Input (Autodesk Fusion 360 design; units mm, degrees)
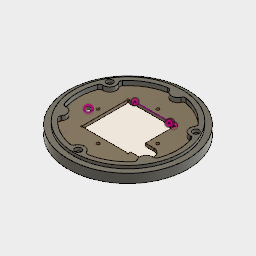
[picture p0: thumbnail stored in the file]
parameter "height" = 12 comment "height of the component"
parameter "rail_height" = 3
parameter "exrtusion_delta_for_magnets" = 0.8
parameter "diameter" = 120
parameter "inner_diameter" = 100
parameter "diameter_offet" = 10
parameter "pressfit_offset" = 1
parameter "magnet_diameter" = 6.4
parameter "magnet_height" = 3.2
parameter "holes_position_from_diameter" = 20
parameter "plateform_height" = 3 (= "height / 4")
parameter "plateform_inner_diameter" = 0
sketch "base" plane through (0, 0, 0) normal (0, 1, 0) x axis (1, 0, 0)
  circle C1 centre (0, 0) radius 60
  circle C2 centre (0, 0) radius 50
  dimension "d1" diameter C1 = 120 (= "diameter")
  dimension "d63" diameter C2 = 100 (= "inner_diameter")
sketch "arround magnets" plane through (0, 0, 0) normal (0, 1, 0) x axis (1, 0, 0)
  circle C1 centre (0, 50) radius 6.4
  point P1 (0, 0)
  point P2 (0, 50)
  dimension "d124" diameter C1 = 12.8 (= "magnet_diameter * 2")
  dimension "d130" distance P1 P2 = 50 (= "diameter / 2 - holes_position_from_diameter / 2")
extrude "Extrude18" new body sketch "arround magnets" along normal blind 12 (= "height")
circular_pattern "C-Pattern6" TotalAngle 360
extrude "Extrude17" new body sketch "base" profile of C2 along normal blind 12 (= "height")
extrude "Extrude8" new body sketch "base" along normal blind 12 (= "height")
combine "Combine2"
sketch "top_holes" plane through (0, 12, 0) normal (0, 1, 0) x axis (-1, 0, 0)
  circle C1 centre (0, 50) radius 3.2
  circle C2 centre (-43.3013, -25) radius 3.2
  circle C3 centre (43.3013, -25) radius 3.2
  point P1 (0, 0)
  point P4 (43.3013, -25)
  dimension "d5" diameter C1 = 6.4 (= "magnet_diameter")
  dimension "d94" distance P1 P4 = 50 (= "diameter / 2 - holes_position_from_diameter / 2")
  dimension "d7" C-Pattern1-Angle = 360
extrude "Extrude13" cut sketch "top_holes" no distance stored
sketch "top_rail_out" plane through (0, 12, 0) normal (0, 1, 0) x axis (-1, 0, 0)
  circle C1 centre (0, 0) radius 60
  circle C2 centre (0, 0) radius 54.5
  circle C3 centre (-43.3013, -25) radius 3.2
  circle C4 centre (0, 50) radius 3.2
  circle C5 centre (43.3013, -25) radius 3.2
  arc A1 centre (-43.3013, 25) radius 6.4 clockwise from (-39.7531, 30.3264) to (-46.14, 19.264)
  arc A2 centre (0, 50) radius 6.4 clockwise from (6.3869, 49.5904) to (-6.3869, 49.5904)
  arc A3 centre (43.3013, 25) radius 6.4 clockwise from (46.14, 19.264) to (39.7531, 30.3264)
  arc A4 centre (43.3013, -25) radius 6.4 clockwise from (39.7531, -30.3264) to (46.14, -19.264)
  arc A5 centre (0, -50) radius 6.4 clockwise from (-6.3869, -49.5904) to (6.3869, -49.5904)
  arc A6 centre (-43.3013, -25) radius 6.4 clockwise from (-46.14, -19.264) to (-39.7531, -30.3264)
  arc A7 centre (0, 0) radius 50 clockwise from (-46.14, -19.264) to (-46.14, 19.264)
  arc A8 centre (0, 0) radius 50 clockwise from (-39.7531, 30.3264) to (-6.3869, 49.5904)
  arc A9 centre (0, 0) radius 50 clockwise from (6.3869, 49.5904) to (39.7531, 30.3264)
  arc A10 centre (0, 0) radius 50 clockwise from (46.14, 19.264) to (46.14, -19.264)
  arc A11 centre (0, 0) radius 50 clockwise from (39.7531, -30.3264) to (6.3869, -49.5904)
  arc A12 centre (0, 0) radius 50 clockwise from (-6.3869, -49.5904) to (-39.7531, -30.3264)
  circle C6 centre (0, 0) radius 60
  dimension "d65" diameter C2 = 109 (= "diameter - diameter_offet - pressfit_offset")
  dimension "d96" diameter C1 = 120 (= "diameter")
extrude "Extrude10" cut sketch "top_rail_out" profile of C1 C2 against normal blind 3 (magnitude of "-1 * rail_height")
sketch "bottom_holes" plane through (0, 0, 0) normal (0, -1, 0) x axis (1, 0, 0)
  circle C1 centre (-43.3013, 25) radius 3.2
  point P1 (0, 0)
  point P2 (-43.3013, 25)
  dimension "d57" diameter C1 = 6.4 (= "magnet_diameter")
  dimension "d95" distance P1 P2 = 50 (= "diameter / 2 - holes_position_from_diameter / 2")
extrude "Extrude14" cut sketch "bottom_holes" no distance stored
sketch "top_rail_in" plane through (0, 12, 0) normal (0, 1, 0) x axis (-1, 0, 0)
  circle C1 centre (0, 0) radius 60
  circle C2 centre (0, 0) radius 50
  circle C3 centre (0, 0) radius 60
  arc A1 centre (-43.3013, 25) radius 6.4 clockwise from (-39.7531, 30.3264) to (-46.14, 19.264)
  arc A2 centre (0, 50) radius 6.4 clockwise from (6.3869, 49.5904) to (-6.3869, 49.5904)
  arc A3 centre (43.3013, 25) radius 6.4 clockwise from (46.14, 19.264) to (39.7531, 30.3264)
  arc A4 centre (43.3013, -25) radius 6.4 clockwise from (39.7531, -30.3264) to (46.14, -19.264)
  arc A5 centre (0, -50) radius 6.4 clockwise from (-6.3869, -49.5904) to (6.3869, -49.5904)
  arc A6 centre (-43.3013, -25) radius 6.4 clockwise from (-46.14, -19.264) to (-39.7531, -30.3264)
  circle C4 centre (-43.3013, -25) radius 3.2
  circle C5 centre (0, 50) radius 3.2
  circle C6 centre (43.3013, -25) radius 3.2
  circle C7 centre (0, 0) radius 54.5
  arc A7 centre (0, 0) radius 50 clockwise from (-46.14, -19.264) to (-46.14, 19.264)
  arc A8 centre (0, 0) radius 50 clockwise from (-39.7531, 30.3264) to (-6.3869, 49.5904)
  arc A9 centre (0, 0) radius 50 clockwise from (6.3869, 49.5904) to (39.7531, 30.3264)
  arc A10 centre (0, 0) radius 50 clockwise from (46.14, 19.264) to (46.14, -19.264)
  arc A11 centre (0, 0) radius 50 clockwise from (39.7531, -30.3264) to (6.3869, -49.5904)
  arc A12 centre (0, 0) radius 50 clockwise from (-6.3869, -49.5904) to (-39.7531, -30.3264)
  dimension "d35" diameter C1 = 120 (= "diameter")
  dimension "d64" diameter C2 = 100 (= "inner_diameter")
  dimension "d66" diameter C3 = 120 (= "diameter")
work_plane "WorkPlane1" AlongDistance -6 (= "-1 * height / 2")
work_point "WorkPoint1"
work_axis "WorkAxis1"
circular_pattern "C-Pattern1" TotalAngle 360
sketch "bottom_rail_out" plane through (0, 0, 0) normal (0, -1, 0) x axis (1, 0, 0)
  circle C1 centre (0, 0) radius 55
  circle C2 centre (0, -50) radius 3.2
  circle C3 centre (43.3013, 25) radius 3.2
  circle C4 centre (-43.3013, 25) radius 3.2
  arc A1 centre (0, -50) radius 6.4 clockwise from (-6.3869, -49.5904) to (6.3869, -49.5904)
  arc A2 centre (-43.3013, 25) radius 55.4401 clockwise from (-46.14, -19.264) to (-39.7531, -30.3264)
  arc A3 centre (-43.3013, 25) radius 6.4 clockwise from (-39.7531, 30.3264) to (-46.14, 19.264)
  arc A4 centre (43.3013, 25) radius 55.4401 clockwise from (6.3869, 49.5904) to (-6.3869, 49.5904)
  arc A5 centre (43.3013, 25) radius 6.4 clockwise from (46.14, 19.264) to (39.7531, 30.3264)
  arc A6 centre (0, -50) radius 55.4401 clockwise from (39.7531, -30.3264) to (46.14, -19.264)
  arc A7 centre (0, 0) radius 50 clockwise from (39.7531, -30.3264) to (6.3869, -49.5904)
  arc A8 centre (0, 0) radius 50 clockwise from (-6.3869, -49.5904) to (-39.7531, -30.3264)
  arc A9 centre (0, 0) radius 50 clockwise from (-46.14, -19.264) to (-46.14, 19.264)
  arc A10 centre (0, 0) radius 50 clockwise from (-39.7531, 30.3264) to (-6.3869, 49.5904)
  arc A11 centre (0, 0) radius 50 clockwise from (6.3869, 49.5904) to (39.7531, 30.3264)
  arc A12 centre (0, 0) radius 50 clockwise from (46.14, 19.264) to (46.14, -19.264)
  circle C5 centre (0, 0) radius 60
  dimension "d67" diameter C1 = 110 (= "diameter - diameter_offet")
extrude "Extrude15" cut sketch "bottom_rail_out" profile of C1 against normal blind 3.8 (magnitude of "-1 * rail_height - exrtusion_delta_for_magnets")
fillet "Fillet3" radius 3
sketch "Sketch19" plane through (0, 0, 0) normal (0, 1, 0) x axis (1, 0, 0)
  circle C1 centre (0, 0) radius 50
  dimension "d134" diameter C1 = 100 (= "inner_diameter")
  dimension "d132" diameter = 0 (= "plateform_inner_diameter")
extrude "Extrude19" add sketch "Sketch19" distance 3 (= "plateform_height") from offset 6 (= "height / 2")
sketch "board_support" plane through (0, 7.5, 0) normal (0, 1, 0) x axis (-1, 0, 0)
  line L1 (-24.5, -24.5) -> (24.5, -24.5)
  line L2 (-24.5, 24.5) -> (-24.5, -24.5)
  line L3 (24.5, 24.5) -> (-24.5, 24.5)
  line L4 (24.5, -24.5) -> (24.5, 24.5)
  line L5 (-24.5, 24.5) -> (24.5, -24.5)
  line L6 (24.5, 24.5) -> (-24.5, -24.5)
  arc A1 centre (-8.6005, 46.2064) radius 3 clockwise from (-9.1495, 49.1557) to (-5.8557, 47.4171)
  arc A2 centre (0, 0) radius 50 clockwise from (-37.9954, 32.5015) to (-9.1495, 49.1557)
  arc A3 centre (-35.7157, 30.5515) radius 3 clockwise from (-38.1366, 28.7797) to (-37.9954, 32.5015)
  arc A4 centre (-43.3013, 25) radius 6.4 clockwise from (-38.1366, 28.7797) to (-43.9923, 18.6374)
  arc A5 centre (-44.3162, 15.6549) radius 3 clockwise from (-47.1449, 16.6542) to (-43.9923, 18.6374)
  arc A6 centre (0, 0) radius 50 clockwise from (-47.1449, -16.6542) to (-47.1449, 16.6542)
  arc A7 centre (-44.3162, -15.6549) radius 3 clockwise from (-43.9923, -18.6374) to (-47.1449, -16.6542)
  arc A8 centre (-43.3013, -25) radius 6.4 clockwise from (-43.9923, -18.6374) to (-38.1366, -28.7797)
  arc A9 centre (-35.7157, -30.5515) radius 3 clockwise from (-37.9954, -32.5015) to (-38.1366, -28.7797)
  arc A10 centre (0, 0) radius 50 clockwise from (-9.1495, -49.1557) to (-37.9954, -32.5015)
  arc A11 centre (-8.6005, -46.2064) radius 3 clockwise from (-5.8557, -47.4171) to (-9.1495, -49.1557)
  arc A12 centre (0, -50) radius 6.4 clockwise from (-5.8557, -47.4171) to (5.8557, -47.4171)
  arc A13 centre (8.6005, -46.2064) radius 3 clockwise from (9.1495, -49.1557) to (5.8557, -47.4171)
  arc A14 centre (0, 0) radius 50 clockwise from (37.9954, -32.5015) to (9.1495, -49.1557)
  arc A15 centre (35.7157, -30.5515) radius 3 clockwise from (38.1366, -28.7797) to (37.9954, -32.5015)
  arc A16 centre (43.3013, -25) radius 6.4 clockwise from (38.1366, -28.7797) to (43.9923, -18.6374)
  arc A17 centre (44.3162, -15.6549) radius 3 clockwise from (47.1449, -16.6542) to (43.9923, -18.6374)
  arc A18 centre (0, 0) radius 50 clockwise from (47.1449, 16.6542) to (47.1449, -16.6542)
  arc A19 centre (44.3162, 15.6549) radius 3 clockwise from (43.9923, 18.6374) to (47.1449, 16.6542)
  arc A20 centre (43.3013, 25) radius 6.4 clockwise from (43.9923, 18.6374) to (38.1366, 28.7797)
  arc A21 centre (35.7157, 30.5515) radius 3 clockwise from (37.9954, 32.5015) to (38.1366, 28.7797)
  arc A22 centre (0, 0) radius 50 clockwise from (9.1495, 49.1557) to (37.9954, 32.5015)
  arc A23 centre (8.6005, 46.2064) radius 3 clockwise from (5.8557, 47.4171) to (9.1495, 49.1557)
  arc A24 centre (0, 50) radius 6.4 clockwise from (5.8557, 47.4171) to (-5.8557, 47.4171)
  point P46 (-24.5, -24.5)
  point P47 (-24.5, 24.5)
  point P48 (24.5, 24.5)
  dimension "d149" distance P46 P47 = 49
  dimension "d150" distance P47 P48 = 49
extrude "Extrude22" cut sketch "board_support" profile of L1 L2 L3 L4 against normal blind 1
sketch "board_hole" plane through (0, 6.5, 0) normal (0, 1, 0) x axis (-1, 0, 0)
  line L1 (-24.5, 24.5) -> (24.5, 24.5)
  line L2 (-24.5, -24.5) -> (-24.5, 24.5)
  line L3 (24.5, -24.5) -> (-24.5, -24.5)
  line L4 (24.5, 24.5) -> (24.5, -24.5)
  line L5 (-23.5, 23.5) -> (23.5, 23.5)
  line L6 (-23.5, -23.5) -> (-23.5, 23.5)
  line L7 (23.5, -23.5) -> (-23.5, -23.5)
  line L8 (23.5, 23.5) -> (23.5, -23.5)
  dimension "d161" = 1
extrude "Extrude25" cut sketch "board_hole" profile of L7 L5 L6 L8 no distance stored
sketch "Sketch27" plane through (0, 7.5, 0) normal (0, 1, 0) x axis (-1, 0, 0)
  line L1 (-23.3, -23.3) -> (23.3, -23.3)
  line L2 (-23.3, 23.3) -> (-23.3, -23.3)
  line L3 (23.3, 23.3) -> (-23.3, 23.3)
  line L4 (23.3, -23.3) -> (23.3, 23.3)
  line L5 (-23.3, 23.3) -> (23.3, -23.3)
  line L6 (23.3, 23.3) -> (-23.3, -23.3)
  line L7 (31.9451, -35.725) -> (31.9451, -13.4168)
  line L8 (31.9451, 25.5084) -> (31.9451, -35.725)
  line L9 (31.9451, -5.9168) -> (31.9451, -20.9168)
  line L10 (23.3, -5.9168) -> (31.9451, -5.9168)
  line L11 (23.3, -20.9168) -> (23.3, -5.9168)
  line L12 (31.9451, -20.9168) -> (23.3, -20.9168)
  line L13 (-31.9451, -6.203) -> (-31.9451, 26.8234)
  line L14 (-31.9451, 20.9168) -> (-31.9451, 5.9168)
  line L15 (-23.3, 20.9168) -> (-31.9451, 20.9168)
  line L16 (-23.3, 5.9168) -> (-23.3, 20.9168)
  line L17 (-31.9451, 5.9168) -> (-23.3, 5.9168)
  line L18 (27.7031, -12.3604) -> (45.2031, -12.3604)
  line L19 (27.7031, 17.6396) -> (27.7031, -12.3604)
  line L20 (45.2031, 17.6396) -> (27.7031, 17.6396)
  line L21 (45.2031, -12.3604) -> (45.2031, 17.6396)
  line L22 (59.3483, 8.8191) -> (0, 0)
  line L23 (34.6199, 5.1445) -> (49.4569, 7.3492)
  line L24 (-17.8201, -24.8) -> (17.8201, -24.8)
  line L25 (0, -30) -> (0, 0)
  line L26 (-17.8201, -21.8) -> (17.8201, -21.8)
  line L27 (17.8201, -24.8) -> (17.8201, -21.8)
  line L28 (-17.8201, -21.8) -> (-17.8201, -24.8)
  circle C1 centre (-30, 0) radius 1.5
  circle C2 centre (0, -30) radius 1.5
  circle C3 centre (30, 0) radius 1.5
  circle C4 centre (0, 30) radius 1.5
  arc A1 centre (-8.6005, 46.2064) radius 3 clockwise from (-9.1495, 49.1557) to (-5.8557, 47.4171)
  arc A2 centre (0, 0) radius 50 clockwise from (-37.9954, 32.5015) to (-9.1495, 49.1557)
  arc A3 centre (-35.7157, 30.5515) radius 3 clockwise from (-38.1366, 28.7797) to (-37.9954, 32.5015)
  arc A4 centre (-43.3013, 25) radius 6.4 clockwise from (-38.1366, 28.7797) to (-43.9923, 18.6374)
  arc A5 centre (-44.3162, 15.6549) radius 3 clockwise from (-47.1449, 16.6542) to (-43.9923, 18.6374)
  arc A6 centre (0, 0) radius 50 clockwise from (-47.1449, -16.6542) to (-47.1449, 16.6542)
  arc A7 centre (-44.3162, -15.6549) radius 3 clockwise from (-43.9923, -18.6374) to (-47.1449, -16.6542)
  arc A8 centre (-43.3013, -25) radius 6.4 clockwise from (-43.9923, -18.6374) to (-38.1366, -28.7797)
  arc A9 centre (-35.7157, -30.5515) radius 3 clockwise from (-37.9954, -32.5015) to (-38.1366, -28.7797)
  arc A10 centre (0, 0) radius 50 clockwise from (-9.1495, -49.1557) to (-37.9954, -32.5015)
  arc A11 centre (-8.6005, -46.2064) radius 3 clockwise from (-5.8557, -47.4171) to (-9.1495, -49.1557)
  arc A12 centre (0, -50) radius 6.4 clockwise from (-5.8557, -47.4171) to (5.8557, -47.4171)
  arc A13 centre (8.6005, -46.2064) radius 3 clockwise from (9.1495, -49.1557) to (5.8557, -47.4171)
  arc A14 centre (0, 0) radius 50 clockwise from (37.9954, -32.5015) to (9.1495, -49.1557)
  arc A15 centre (35.7157, -30.5515) radius 3 clockwise from (38.1366, -28.7797) to (37.9954, -32.5015)
  arc A16 centre (43.3013, -25) radius 6.4 clockwise from (38.1366, -28.7797) to (43.9923, -18.6374)
  arc A17 centre (44.3162, -15.6549) radius 3 clockwise from (47.1449, -16.6542) to (43.9923, -18.6374)
  arc A18 centre (0, 0) radius 50 clockwise from (47.1449, 16.6542) to (47.1449, -16.6542)
  arc A19 centre (44.3162, 15.6549) radius 3 clockwise from (43.9923, 18.6374) to (47.1449, 16.6542)
  arc A20 centre (43.3013, 25) radius 6.4 clockwise from (43.9923, 18.6374) to (38.1366, 28.7797)
  arc A21 centre (35.7157, 30.5515) radius 3 clockwise from (37.9954, 32.5015) to (38.1366, 28.7797)
  arc A22 centre (0, 0) radius 50 clockwise from (9.1495, 49.1557) to (37.9954, 32.5015)
  arc A23 centre (8.6005, 46.2064) radius 3 clockwise from (5.8557, 47.4171) to (9.1495, 49.1557)
  arc A24 centre (0, 50) radius 6.4 clockwise from (5.8557, 47.4171) to (-5.8557, 47.4171)
  circle C5 centre (23.3, -23.3) radius 0.8
  circle C6 centre (-23.3, -23.3) radius 0.8
  circle C7 centre (23.3, 23.3) radius 0.8
  circle C8 centre (-23.3, 23.3) radius 0.8
  circle C9 centre (0, 0) radius 34.6482
  circle C10 centre (31.9451, -13.4168) radius 7.5
  circle C11 centre (-31.9451, 13.4168) radius 7.5
  circle C12 centre (0, 0) radius 60
  circle C13 centre (34.6199, 5.1445) radius 3.35
  point P2 (-30, 0)
  point P3 (0, 0)
  point P51 (-23.3, -23.3)
  point P52 (-23.3, 23.3)
  point P53 (23.3, 23.3)
  point P75 (45.2031, -12.3604)
  point P76 (27.7031, -12.3604)
  point P78 (45.2031, 17.6396)
  point P82 (49.4569, 7.3492)
  point P83 (34.6199, 5.1445)
  point P85 (17.8201, -24.8)
  point P86 (-17.8201, -24.8)
  point P89 (17.8201, -21.8)
  dimension "d156" diameter C1 = 3
  dimension "d157" distance P2 P3 = 30
  dimension "d164" distance P51 P52 = 46.6
  dimension "d165" distance P52 P53 = 46.6
  dimension "d166" diameter C5 = 1.6
  dimension "d171" diameter C10 = 15
  dimension "d175" distance P75 P76 = 17.5
  dimension "d176" distance P75 P78 = 30
  dimension "d178" distance P82 P83 = 15
  dimension "d179" diameter C13 = 6.7
  dimension "d180" distance P85 P86 = 35.6403
  dimension "d181" distance P85 P89 = 3
  dimension "d159" C-Pattern1-Angle = 360
  dimension "d169" R-Pattern1-uDistance = -46.6
  dimension "d170" R-Pattern1-vDistance = 46.6
  dimension "d173" C-Pattern2-Angle = 360
chamfer "Chamfer1" distance 1
extrude "Extrude24" cut sketch "Sketch27" profile of C1 C2 C3 C4 L1 L2 L3 L4 C5 C6 C7 C8 C11 L11 L13 L14 L15 L16 L17 C13 L24 L26 L27 L28 no distance stored
sketch "Sketch28" plane through (0, 7.5, 0) normal (0, 1, 0) x axis (-1, 0, 0)
  line L1 (22.5, 23.3) -> (-22.5, 23.3)
  line L2 (23.3, -22.5) -> (23.3, 22.5)
  line L3 (17.8201, -23.3) -> (22.5, -23.3)
  line L4 (-23.3, 5.9168) -> (-23.3, -22.5)
  line L5 (-31.9451, 5.9168) -> (-23.3, 5.9168)
  line L6 (-23.3, 20.9168) -> (-31.9451, 20.9168)
  line L7 (-23.3, 22.5) -> (-23.3, 20.9168)
  line L8 (17.8201, -24.8) -> (17.8201, -23.3)
  line L9 (-17.8201, -24.8) -> (17.8201, -24.8)
  line L10 (-17.8201, -23.3) -> (-17.8201, -24.8)
  line L11 (-22.5, -23.3) -> (-17.8201, -23.3)
  circle C1 centre (-30, 0) radius 1.5
  circle C2 centre (30, 0) radius 1.5
  circle C3 centre (0, -30) radius 1.5
  circle C4 centre (0, 30) radius 1.5
  arc A1 centre (23.3, 23.3) radius 0.8 clockwise from (22.5, 23.3) to (23.3, 22.5)
  arc A2 centre (23.3, -23.3) radius 0.8 clockwise from (23.3, -22.5) to (22.5, -23.3)
  arc A3 centre (-23.3, -23.3) radius 0.8 clockwise from (-22.5, -23.3) to (-23.3, -22.5)
  arc A4 centre (-31.9451, 13.4168) radius 7.5 clockwise from (-31.9451, 5.9168) to (-31.9451, 20.9168)
  arc A5 centre (-23.3, 23.3) radius 0.8 clockwise from (-23.3, 22.5) to (-22.5, 23.3)
  arc A6 centre (-8.6005, 46.2064) radius 3 clockwise from (-9.1495, 49.1557) to (-5.8557, 47.4171)
  arc A7 centre (0, 0) radius 50 clockwise from (-37.9954, 32.5015) to (-9.1495, 49.1557)
  arc A8 centre (-35.7157, 30.5515) radius 3 clockwise from (-38.1366, 28.7797) to (-37.9954, 32.5015)
  arc A9 centre (-43.3013, 25) radius 6.4 clockwise from (-38.1366, 28.7797) to (-43.9923, 18.6374)
  arc A10 centre (-44.3162, 15.6549) radius 3 clockwise from (-47.1449, 16.6542) to (-43.9923, 18.6374)
  arc A11 centre (0, 0) radius 50 clockwise from (-47.1449, -16.6542) to (-47.1449, 16.6542)
  arc A12 centre (-44.3162, -15.6549) radius 3 clockwise from (-43.9923, -18.6374) to (-47.1449, -16.6542)
  arc A13 centre (-43.3013, -25) radius 6.4 clockwise from (-43.9923, -18.6374) to (-38.1366, -28.7797)
  arc A14 centre (-35.7157, -30.5515) radius 3 clockwise from (-37.9954, -32.5015) to (-38.1366, -28.7797)
  arc A15 centre (0, 0) radius 50 clockwise from (-9.1495, -49.1557) to (-37.9954, -32.5015)
  arc A16 centre (-8.6005, -46.2064) radius 3 clockwise from (-5.8557, -47.4171) to (-9.1495, -49.1557)
  arc A17 centre (0, -50) radius 6.4 clockwise from (-5.8557, -47.4171) to (5.8557, -47.4171)
  arc A18 centre (8.6005, -46.2064) radius 3 clockwise from (9.1495, -49.1557) to (5.8557, -47.4171)
  arc A19 centre (0, 0) radius 50 clockwise from (37.9954, -32.5015) to (9.1495, -49.1557)
  arc A20 centre (35.7157, -30.5515) radius 3 clockwise from (38.1366, -28.7797) to (37.9954, -32.5015)
  arc A21 centre (43.3013, -25) radius 6.4 clockwise from (38.1366, -28.7797) to (43.9923, -18.6374)
  arc A22 centre (44.3162, -15.6549) radius 3 clockwise from (47.1449, -16.6542) to (43.9923, -18.6374)
  arc A23 centre (0, 0) radius 50 clockwise from (47.1449, 16.6542) to (47.1449, -16.6542)
  arc A24 centre (44.3162, 15.6549) radius 3 clockwise from (43.9923, 18.6374) to (47.1449, 16.6542)
  arc A25 centre (43.3013, 25) radius 6.4 clockwise from (43.9923, 18.6374) to (38.1366, 28.7797)
  arc A26 centre (35.7157, 30.5515) radius 3 clockwise from (37.9954, 32.5015) to (38.1366, 28.7797)
  arc A27 centre (0, 0) radius 50 clockwise from (9.1495, 49.1557) to (37.9954, 32.5015)
  arc A28 centre (8.6005, 46.2064) radius 3 clockwise from (5.8557, 47.4171) to (9.1495, 49.1557)
  arc A29 centre (0, 50) radius 6.4 clockwise from (5.8557, 47.4171) to (-5.8557, 47.4171)
  circle C5 centre (34.6199, 5.1445) radius 3.35
named bodies: "Part A Top"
